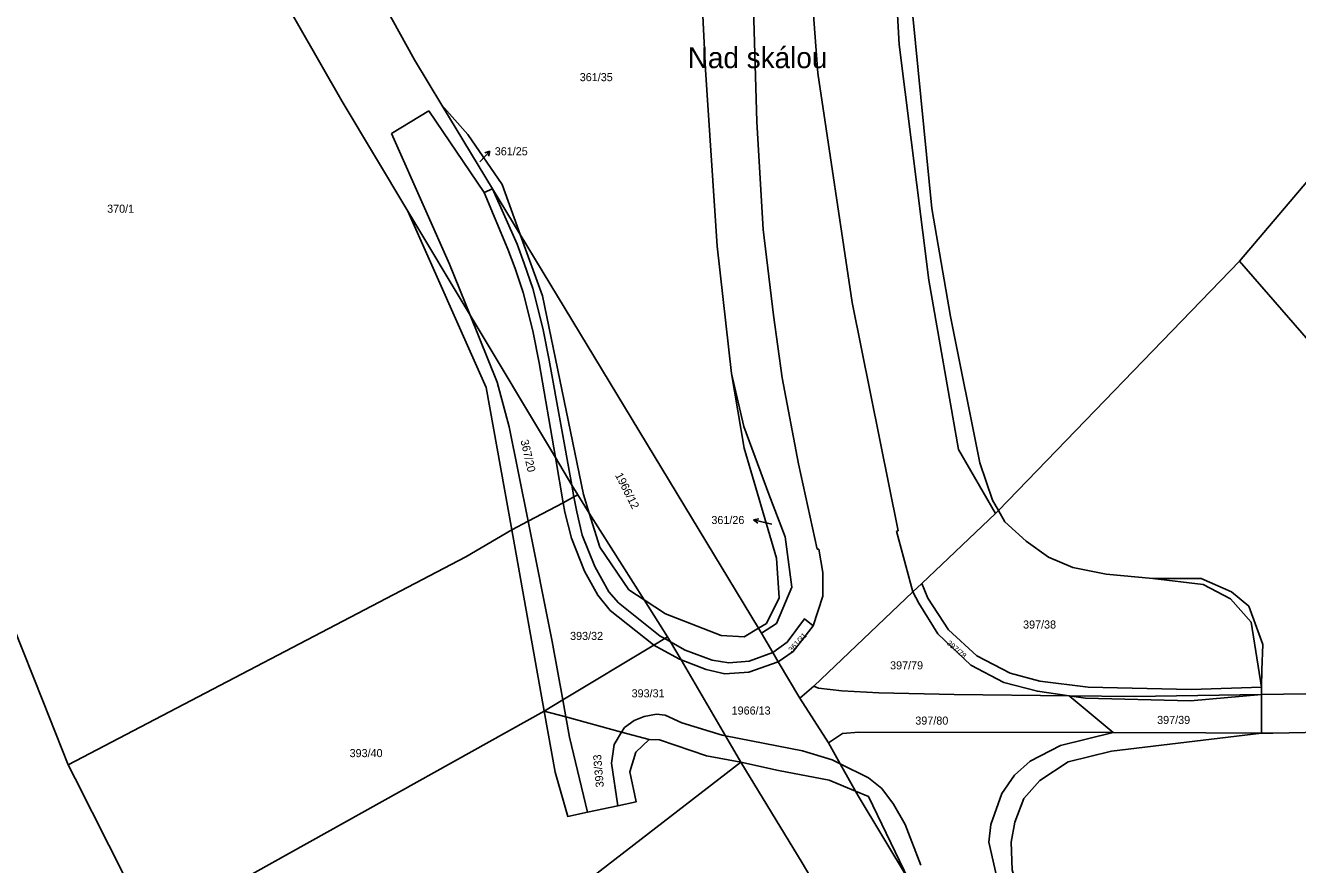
# Model space of a CAD drawing. Extents: x -679220 to -673243, y -1075091 to -1066557.
# Drawn here: x -675653.7 to -675385.5, y -1072983.5 to -1072806.7 of the extents above; entities that cross this region are included whole.
import ezdxf

# ---------------------------------------------------------------- set-up
doc = ezdxf.new("R2010")
doc.units = 0
for name, color, linetype in [('Hranice kat_území', 7, 'Continuous'), ('Hranice parcel', 7, 'Continuous'), ('Parcelní čísla', 7, 'Continuous'), ('Pop  PČ popisy', 7, 'Continuous'), ('Vnitřní kresba', 7, 'Continuous')]:
    doc.layers.add(name, color=color, linetype=linetype)

msp = doc.modelspace()

# ---------------------------------------------------------------- linework, layer by layer
at = {"layer": 'Hranice kat_území'}
for p, q in [((-675650.06, -1072949), (-675656.29, -1072933.27)), ((-675644.7, -1072962.47), (-675650.06, -1072949)), ((-675643.23, -1072965.33), (-675644.7, -1072962.47)), ((-675632.56, -1072986.48), (-675643.23, -1072965.33))]:
    msp.add_line(p, q, dxfattribs=at)
at = {"layer": 'Hranice parcel'}
for p, q in [((-675499.17, -1072933.67), (-675549.4, -1072850.74)), ((-675448.52, -1072908.9), (-675397.73, -1072856.39)), ((-675537.26, -1072905.62), (-675534.84, -1072909.44)), ((-675523.27, -1072927.7), (-675534.84, -1072909.44)), ((-675544.33, -1072951.13), (-675551.19, -1072912.99)), ((-675466.61, -1072926.05), (-675464.74, -1072924.28)), ((-675518.31, -1072935.52), (-675523.27, -1072927.7)), ((-675487.51, -1072945.87), (-675466.61, -1072926.05)), ((-675498.51, -1072934.76), (-675499.17, -1072933.67)), ((-675498.51, -1072934.76), (-675496.15, -1072938.78)), ((-675495, -1072940.74), (-675496.15, -1072938.78)), ((-675495, -1072940.74), (-675490.47, -1072948.45)), ((-675490.47, -1072948.45), (-675487.51, -1072945.87)), ((-675393.08, -1072947.67), (-675393.12, -1072946.11)), ((-675484.4, -1072957.84), (-675490.47, -1072948.45)), ((-675433.64, -1072947.93), (-675424.34, -1072955.68)), ((-675393.08, -1072955.78), (-675393.08, -1072947.67)), ((-675544.33, -1072951.13), (-675627.09, -1072997.24))]:
    msp.add_line(p, q, dxfattribs=at)
for points in [[(-675448.52, -1072908.9), (-675449.85, -1072906.74), (-675452.49, -1072898.87), (-675458.7, -1072868), (-675462.64, -1072845.24), (-675466.61, -1072804.78), (-675468.02, -1072784.34), (-675468.66, -1072759.35), (-675468.62, -1072738.95), (-675468.34, -1072723.01)], [(-675397.73, -1072856.39), (-675381.14, -1072836.83), (-675324.75, -1072774.52), (-675290.4, -1072737.5)], [(-675634.82, -1072740.31), (-675625.19, -1072755.93), (-675586.95, -1072822.71), (-675573.11, -1072845.8)], [(-675513.21, -1072757.8), (-675512.46, -1072773.25), (-675510.33, -1072816.05), (-675507.9, -1072853.17), (-675504.88, -1072880.03)], [(-675565.89, -1072823.51), (-675571.67, -1072813.96), (-675577.95, -1072802.67)], [(-675549.4, -1072850.74), (-675553.23, -1072840.18), (-675560.42, -1072829.68), (-675565.89, -1072823.51)], [(-675549.4, -1072850.74), (-675555.21, -1072841.14), (-675565.89, -1072823.51)], [(-675551.19, -1072912.99), (-675556.59, -1072882.96), (-675573.11, -1072845.8)], [(-675573.11, -1072845.8), (-675559.96, -1072867.74), (-675541.98, -1072897.74), (-675538.52, -1072903.52), (-675537.26, -1072905.62)], [(-675534.84, -1072909.44), (-675536.06, -1072905.51), (-675544.7, -1072863.68), (-675549.4, -1072850.74)], [(-675397.73, -1072856.39), (-675375.67, -1072881.73), (-675363.62, -1072896.67)], [(-675504.88, -1072880.03), (-675502.17, -1072895.75), (-675495.39, -1072918.93), (-675494.8, -1072927.3), (-675497.49, -1072932.66), (-675499.17, -1072933.67)], [(-675504.88, -1072880.03), (-675502.26, -1072891.2), (-675496.95, -1072905.48), (-675493.55, -1072914.44), (-675492.11, -1072925.02), (-675495.38, -1072932.7), (-675498.51, -1072934.76)], [(-675551.19, -1072912.99), (-675547.71, -1072911.15), (-675540.35, -1072907.25), (-675538.06, -1072906.04), (-675537.26, -1072905.62)], [(-675464.74, -1072924.28), (-675449.15, -1072909.49), (-675448.52, -1072908.9)], [(-675393.12, -1072946.11), (-675393.01, -1072942.48), (-675392.81, -1072937.09), (-675395.77, -1072929.05), (-675399.45, -1072926.02), (-675405.79, -1072923.18), (-675416.01, -1072923.18), (-675425.83, -1072922.33), (-675432.88, -1072920.91), (-675437.99, -1072918.74), (-675442.69, -1072915.33), (-675447.19, -1072911.26), (-675448.52, -1072908.9)], [(-675551.19, -1072912.99), (-675560.89, -1072918.63), (-675644.7, -1072962.47)], [(-675464.74, -1072924.28), (-675463.43, -1072927.33), (-675459.09, -1072934.02), (-675453.1, -1072939.52), (-675446.1, -1072943.16), (-675439.87, -1072944.84), (-675429.66, -1072946.11), (-675407.94, -1072946.63), (-675393.12, -1072946.11)], [(-675523.27, -1072927.7), (-675518.75, -1072930.64), (-675507.01, -1072935.24), (-675502.17, -1072935.48), (-675499.17, -1072933.67)], [(-675466.61, -1072926.05), (-675465.35, -1072928.43), (-675461.31, -1072934.89), (-675454.38, -1072941.48), (-675447.42, -1072945.13), (-675440.33, -1072946.97), (-675433.64, -1072947.93)], [(-675496.15, -1072938.78), (-675493.13, -1072936.64), (-675489.42, -1072931.68), (-675487.61, -1072933.17), (-675491.87, -1072938.62), (-675495, -1072940.74)], [(-675518.31, -1072935.52), (-675518.93, -1072935.89), (-675521.19, -1072937.25), (-675540.42, -1072948.79), (-675544.33, -1072951.13)], [(-675502.85, -1072961.9), (-675506.1, -1072956.35), (-675515.48, -1072940.35), (-675517.69, -1072936.57), (-675518.31, -1072935.52)], [(-675330.81, -1072937.87), (-675335.1, -1072939.14), (-675346.31, -1072942.25), (-675364.71, -1072946.32), (-675379.09, -1072947.45), (-675393.08, -1072947.67)], [(-675487.51, -1072945.87), (-675486.49, -1072946.33), (-675481.61, -1072946.85), (-675473.78, -1072947.27), (-675457.87, -1072947.67), (-675433.64, -1072947.93)], [(-675393.08, -1072947.67), (-675419.96, -1072948.08), (-675433.64, -1072947.93)], [(-675334.85, -1072947.18), (-675354.01, -1072951.9), (-675364.06, -1072953.71), (-675373.08, -1072954.94), (-675380.47, -1072955.59), (-675390.73, -1072955.79), (-675393.08, -1072955.78)], [(-675522.23, -1072957.15), (-675525.03, -1072959.77), (-675526.25, -1072963.91), (-675524.97, -1072970.28), (-675528.82, -1072971.09), (-675535.21, -1072972.44), (-675539.37, -1072973.32), (-675542.02, -1072964), (-675544.33, -1072951.13)], [(-675544.33, -1072951.13), (-675539.77, -1072952.37), (-675528.01, -1072955.58), (-675522.23, -1072957.15)], [(-675502.85, -1072961.9), (-675510.12, -1072960.57), (-675520.05, -1072957.18), (-675522.23, -1072957.15)], [(-675424.34, -1072955.68), (-675477.98, -1072955.6), (-675481.46, -1072955.84), (-675484.4, -1072957.84)], [(-675393.08, -1072955.78), (-675424.7, -1072959.62), (-675433.88, -1072961.82), (-675439.83, -1072965.75), (-675443.23, -1072969.53), (-675445.13, -1072974.54), (-675445.9, -1072978.75), (-675445.68, -1072984.61), (-675444.24, -1072989.34), (-675439.35, -1073001.36), (-675432.66, -1073017.09), (-675428.37, -1073030.15), (-675423.46, -1073041.93), (-675410.58, -1073071.73), (-675398.79, -1073094.57)], [(-675424.34, -1072955.68), (-675404.85, -1072955.71), (-675393.08, -1072955.78)], [(-675484.4, -1072957.84), (-675481.91, -1072962.27), (-675478.7, -1072968)], [(-675596.64, -1073024.04), (-675582.08, -1073016.73), (-675550.47, -1072998.63), (-675502.85, -1072961.9)], [(-675502.85, -1072961.9), (-675494.92, -1072963.63), (-675484.24, -1072965.68), (-675478.7, -1072968)], [(-675481.85, -1072996.78), (-675489.97, -1072983.1), (-675502.85, -1072961.9)], [(-675478.7, -1072968), (-675478.13, -1072969), (-675467.54, -1072986.63)]]:
    msp.add_lwpolyline(points, dxfattribs=at)
at = {"layer": 'Pop  PČ popisy'}
for p, q in [((-675557.86, -1072835.36), (-675555.78, -1072833.2)), ((-675555.78, -1072833.2), (-675556.83, -1072833.57)), ((-675555.78, -1072833.2), (-675556.11, -1072834.27)), ((-675557.93, -1072835.43), (-675557.86, -1072835.36)), ((-675500.18, -1072910.88), (-675499.1, -1072910.61)), ((-675497.26, -1072911.55), (-675500.18, -1072910.88)), ((-675500.18, -1072910.88), (-675499.32, -1072911.59)), ((-675496.31, -1072911.76), (-675497.26, -1072911.55))]:
    msp.add_line(p, q, dxfattribs=at)
at = {"layer": 'Vnitřní kresba'}
for p, q in [((-675490.2, -1072767.27), (-675486.67, -1072816.73)), ((-675471.99, -1072767.75), (-675469.47, -1072810.74)), ((-675499.49, -1072827.02), (-675500.64, -1072787.2)), ((-675469.47, -1072810.74), (-675463.23, -1072860.34)), ((-675486.67, -1072816.73), (-675479.39, -1072865.04)), ((-675576.55, -1072829.49), (-675568.69, -1072824.69)), ((-675568.69, -1072824.69), (-675557, -1072841.93)), ((-675498.17, -1072849.71), (-675499.49, -1072827.02)), ((-675569.32, -1072845.75), (-675576.55, -1072829.49)), ((-675557, -1072841.93), (-675555.21, -1072841.14)), ((-675551.98, -1072853.85), (-675557, -1072841.93)), ((-675550.05, -1072852.81), (-675555.21, -1072841.14)), ((-675564.33, -1072856.99), (-675569.32, -1072845.75)), ((-675496.01, -1072867.77), (-675498.17, -1072849.71)), ((-675548.53, -1072856.87), (-675550.05, -1072852.81)), ((-675550.43, -1072857.94), (-675551.98, -1072853.85)), ((-675559.96, -1072867.74), (-675564.33, -1072856.99)), ((-675548.8, -1072862.99), (-675550.43, -1072857.94)), ((-675546.73, -1072862.15), (-675548.53, -1072856.87)), ((-675463.23, -1072860.34), (-675456.99, -1072896.02)), ((-675547.8, -1072866.81), (-675548.8, -1072862.99)), ((-675545.74, -1072865.99), (-675546.73, -1072862.15)), ((-675545.74, -1072865.99), (-675544.52, -1072870.85)), ((-675469.7, -1072913.14), (-675479.39, -1072865.04)), ((-675554.24, -1072881.82), (-675559.96, -1072867.74)), ((-675546.67, -1072871.42), (-675547.8, -1072866.81)), ((-675494.17, -1072880.91), (-675496.01, -1072867.77)), ((-675545.41, -1072877.79), (-675546.67, -1072871.42)), ((-675544.52, -1072870.85), (-675543.31, -1072877.19)), ((-675543.31, -1072877.19), (-675538.52, -1072903.52)), ((-675541.98, -1072897.74), (-675545.41, -1072877.79)), ((-675551.69, -1072891.23), (-675554.24, -1072881.82)), ((-675490.71, -1072899.04), (-675494.17, -1072880.91)), ((-675547.71, -1072911.15), (-675551.69, -1072891.23)), ((-675449.15, -1072909.49), (-675456.99, -1072896.02)), ((-675540.35, -1072907.25), (-675541.98, -1072897.74)), ((-675490.71, -1072899.04), (-675486.78, -1072917.05)), ((-675538.52, -1072903.52), (-675538.06, -1072906.04)), ((-675538.06, -1072906.04), (-675537.49, -1072909.16)), ((-675540.01, -1072909.21), (-675540.35, -1072907.25)), ((-675538.57, -1072914.69), (-675540.01, -1072909.21)), ((-675536.36, -1072914.11), (-675537.49, -1072909.16)), ((-675542.65, -1072936.49), (-675547.71, -1072911.15)), ((-675534.84, -1072909.44), (-675532.61, -1072916.63)), ((-675535.81, -1072921.66), (-675538.57, -1072914.69)), ((-675533.66, -1072920.69), (-675536.36, -1072914.11)), ((-675469.7, -1072913.14), (-675470.03, -1072913.22)), ((-675470.03, -1072913.22), (-675466.61, -1072926.05)), ((-675532.61, -1072916.63), (-675526.49, -1072925.6)), ((-675486.78, -1072917.05), (-675486.45, -1072917.06)), ((-675486.45, -1072917.06), (-675485.59, -1072921.96)), ((-675533.01, -1072926.73), (-675535.81, -1072921.66)), ((-675530.72, -1072926.01), (-675533.66, -1072920.69)), ((-675485.59, -1072921.96), (-675485.6, -1072926.95)), ((-675416.01, -1072923.18), (-675405.38, -1072924.45)), ((-675405.38, -1072924.45), (-675399.64, -1072927.51)), ((-675530.44, -1072929.97), (-675533.01, -1072926.73)), ((-675528.69, -1072928.33), (-675530.72, -1072926.01)), ((-675526.49, -1072925.6), (-675523.27, -1072927.7)), ((-675485.6, -1072926.95), (-675487.61, -1072933.17)), ((-675399.64, -1072927.51), (-675395.3, -1072932.44)), ((-675521.32, -1072937.18), (-675530.44, -1072929.97)), ((-675519.88, -1072935.36), (-675528.69, -1072928.33)), ((-675395.3, -1072932.44), (-675393.12, -1072946.11)), ((-675519.88, -1072935.36), (-675518.93, -1072935.89)), ((-675518.93, -1072935.89), (-675517.69, -1072936.57)), ((-675540.42, -1072948.79), (-675542.65, -1072936.49)), ((-675521.19, -1072937.25), (-675521.32, -1072937.18)), ((-675515.95, -1072940.17), (-675521.19, -1072937.25)), ((-675517.69, -1072936.57), (-675514.58, -1072938.3)), ((-675514.58, -1072938.3), (-675508.91, -1072940.39)), ((-675501.09, -1072940.6), (-675496.15, -1072938.78)), ((-675515.48, -1072940.35), (-675515.95, -1072940.17)), ((-675510.22, -1072942.36), (-675515.48, -1072940.35)), ((-675508.91, -1072940.39), (-675505.4, -1072940.97)), ((-675505.4, -1072940.97), (-675501.09, -1072940.6)), ((-675495, -1072940.74), (-675501.16, -1072942.92)), ((-675506.23, -1072943.27), (-675510.22, -1072942.36)), ((-675501.16, -1072942.92), (-675506.23, -1072943.27)), ((-675539.77, -1072952.37), (-675540.42, -1072948.79)), ((-675430.24, -1072948.42), (-675433.64, -1072947.93)), ((-675408.05, -1072948.97), (-675430.24, -1072948.42)), ((-675393.08, -1072947.67), (-675408.05, -1072948.97)), ((-675523.26, -1072952.26), (-675525.39, -1072953.14)), ((-675520.63, -1072951.82), (-675523.26, -1072952.26)), ((-675518.82, -1072952), (-675520.63, -1072951.82)), ((-675515.35, -1072953.62), (-675518.82, -1072952)), ((-675539, -1072956.66), (-675539.77, -1072952.37)), ((-675527.41, -1072954.6), (-675528.01, -1072955.58)), ((-675525.39, -1072953.14), (-675527.41, -1072954.6)), ((-675506.81, -1072956.21), (-675515.35, -1072953.62)), ((-675535.21, -1072972.44), (-675539, -1072956.66)), ((-675528.01, -1072955.58), (-675529.62, -1072958.2)), ((-675506.1, -1072956.35), (-675506.81, -1072956.21)), ((-675489.87, -1072959.53), (-675506.1, -1072956.35)), ((-675424.34, -1072955.68), (-675435.46, -1072958.43)), ((-675529.62, -1072958.2), (-675530.15, -1072962.12)), ((-675483.63, -1072961.42), (-675489.87, -1072959.53)), ((-675435.46, -1072958.43), (-675441.85, -1072961.72)), ((-675530.15, -1072962.12), (-675528.82, -1072971.09)), ((-675481.91, -1072962.27), (-675483.63, -1072961.42)), ((-675475.98, -1072965.21), (-675481.91, -1072962.27)), ((-675441.85, -1072961.72), (-675445.21, -1072964.64)), ((-675473.15, -1072967.44), (-675475.98, -1072965.21)), ((-675445.21, -1072964.64), (-675447.85, -1072968.49)), ((-675478.7, -1072968), (-675475.95, -1072969.14)), ((-675470.71, -1072970.79), (-675473.15, -1072967.44)), ((-675475.95, -1072969.14), (-675467.54, -1072986.63)), ((-675468.2, -1072975.05), (-675470.71, -1072970.79)), ((-675447.85, -1072968.49), (-675450.15, -1072975.04)), ((-675464.94, -1072983.59), (-675468.2, -1072975.05)), ((-675450.15, -1072975.04), (-675450.62, -1072978.77)), ((-675450.62, -1072978.77), (-675448.28, -1072988.97))]:
    msp.add_line(p, q, dxfattribs=at)

# ---------------------------------------------------------------- texts
at = {"layer": 'Parcelní čísla'}
for s, p in [('361/35', (-675536.84, -1072818.44)), ('361/25', (-675554.76, -1072834.06)), ('370/1', (-675636.49, -1072846.16)), ('361/26', (-675509.09, -1072911.74)), ('397/38', (-675443.37, -1072933.76)), ('393/32', (-675538.88, -1072936.16)), ('397/79', (-675471.41, -1072942.36)), ('393/31', (-675525.91, -1072948.25)), ('1966/13', (-675504.82, -1072951.88)), ('397/80', (-675466.09, -1072954)), ('397/39', (-675415.1, -1072953.86)), ('393/40', (-675585.37, -1072960.85))]:
    msp.add_text(s, height=1.7, dxfattribs=at).set_placement(p)
for s, height, rotation, p in [('367/20', 1.7, 283, (-675549.34, -1072894.16)), ('1966/12', 1.7, 297, (-675529.45, -1072901.44)), ('361/31', 1.14, 47, (-675492.16, -1072938.83)), ('397/78', 1.14, 319, (-675459.56, -1072936.99)), ('393/33', 1.7, 95, (-675531.75, -1072967.15))]:
    msp.add_text(s, height=height, rotation=rotation, dxfattribs=at).set_placement(p)
at = {"layer": 'Pop  PČ popisy'}
msp.add_text('Nad skálou', height=4.4, dxfattribs=at).set_placement((-675514.07, -1072815.7))

doc.saveas('drawing.dxf')
